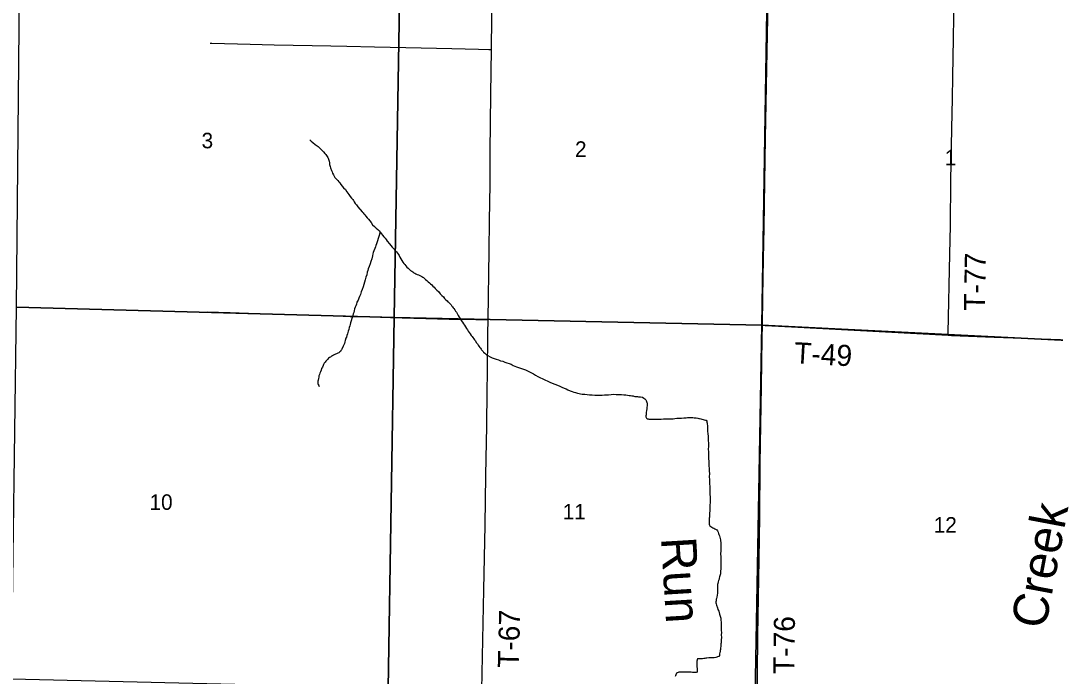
# Model space of a CAD drawing. Extents: x 1587405 to 1714697, y 1028970 to 1155083.
# Drawn here: x 1634826 to 1649563, y 1082468 to 1091803 of the extents above; entities that cross this region are included whole.
import ezdxf

# ---------------------------------------------------------------- set-up
doc = ezdxf.new("R2010")
doc.units = 0
for name, color, linetype in [('GM_X_Minor_River', 7, 'Continuous'), ('GM_X_Minor_River_Text', 7, 'Continuous'), ('GM_X_Section', 7, 'Continuous'), ('GM_X_Section_Text', 7, 'Continuous'), ('GM_X_Township_Road', 7, 'Continuous'), ('GM_X_Township_Road_Text', 7, 'Continuous')]:
    doc.layers.add(name, color=color, linetype=linetype)

msp = doc.modelspace()

# ---------------------------------------------------------------- linework, layer by layer
at = {"layer": 'GM_X_Minor_River'}
for points in [[(1638945, 1090105), (1638963, 1090089), (1638987, 1090067), (1639021, 1090042), (1639061, 1090012), (1639085, 1089989), (1639107, 1089967), (1639127, 1089951), (1639141, 1089934), (1639157, 1089914), (1639173, 1089896), (1639184, 1089882), (1639192, 1089870), (1639200, 1089857), (1639204, 1089847), (1639210, 1089831), (1639216, 1089819), (1639220, 1089801), (1639224, 1089779), (1639227, 1089753), (1639233, 1089726), (1639237, 1089708), (1639243, 1089692), (1639247, 1089682), (1639253, 1089668), (1639261, 1089650), (1639268, 1089632), (1639282, 1089607), (1639292, 1089589), (1639302, 1089571), (1639314, 1089557), (1639324, 1089547), (1639332, 1089537), (1639342, 1089526), (1639356, 1089510), (1639370, 1089492), (1639387, 1089470), (1639407, 1089447), (1639425, 1089421), (1639451, 1089397), (1639473, 1089364), (1639499, 1089330), (1639520, 1089299), (1639540, 1089275), (1639556, 1089257), (1639566, 1089241), (1639578, 1089222), (1639592, 1089202), (1639608, 1089180), (1639630, 1089152), (1639691, 1089083), (1639703, 1089068), (1639715, 1089054), (1639729, 1089038), (1639743, 1089020), (1639761, 1088998), (1639781, 1088975), (1639798, 1088953), (1639816, 1088929), (1639838, 1088896), (1639868, 1088874), (1639890, 1088849), (1639912, 1088829), (1639932, 1088811), (1639948, 1088793), (1639963, 1088770), (1639981, 1088748), (1639997, 1088726), (1640017, 1088705), (1640031, 1088687), (1640047, 1088665), (1640079, 1088628), (1640100, 1088604), (1640118, 1088580), (1640140, 1088555), (1640160, 1088533), (1640178, 1088513), (1640194, 1088495), (1640206, 1088476), (1640216, 1088458), (1640227, 1088436), (1640239, 1088414), (1640253, 1088387), (1640269, 1088367), (1640285, 1088347), (1640299, 1088331), (1640313, 1088312), (1640327, 1088294), (1640344, 1088280), (1640360, 1088264), (1640380, 1088247), (1640398, 1088237), (1640412, 1088225), (1640426, 1088215), (1640442, 1088207), (1640454, 1088198), (1640474, 1088188), (1640490, 1088182), (1640538, 1088161), (1640552, 1088153), (1640564, 1088145)], [(1639948, 1088793), (1639902, 1088654), (1639898, 1088640), (1639892, 1088624), (1639885, 1088604), (1639879, 1088582), (1639848, 1088504), (1639844, 1088484), (1639836, 1088454), (1639827, 1088414), (1639815, 1088374), (1639802, 1088340), (1639788, 1088302), (1639776, 1088272), (1639769, 1088248), (1639763, 1088220), (1639755, 1088184), (1639744, 1088150), (1639734, 1088114), (1639724, 1088080), (1639713, 1088048), (1639703, 1088014), (1639690, 1087977), (1639676, 1087941), (1639664, 1087905), (1639651, 1087877), (1639641, 1087851), (1639631, 1087825), (1639616, 1087793), (1639608, 1087769), (1639600, 1087745), (1639591, 1087723), (1639583, 1087699), (1639575, 1087673), (1639569, 1087649), (1639562, 1087627), (1639556, 1087605), (1639550, 1087585), (1639542, 1087561), (1639535, 1087529), (1639525, 1087503), (1639517, 1087479), (1639512, 1087459), (1639504, 1087433), (1639498, 1087405), (1639492, 1087383), (1639485, 1087363), (1639479, 1087343), (1639471, 1087321), (1639465, 1087299), (1639458, 1087281), (1639448, 1087251), (1639442, 1087229), (1639436, 1087209), (1639427, 1087189), (1639421, 1087169), (1639401, 1087125), (1639395, 1087115), (1639388, 1087105), (1639382, 1087095), (1639368, 1087081), (1639358, 1087075), (1639342, 1087067), (1639332, 1087063), (1639322, 1087059), (1639312, 1087055), (1639301, 1087049), (1639291, 1087045), (1639281, 1087039), (1639269, 1087033), (1639253, 1087024), (1639241, 1087014), (1639227, 1087006), (1639212, 1086996), (1639200, 1086982), (1639186, 1086970), (1639174, 1086954), (1639162, 1086940), (1639151, 1086926), (1639141, 1086910), (1639133, 1086894), (1639125, 1086872), (1639113, 1086850), (1639104, 1086826), (1639096, 1086804), (1639088, 1086784), (1639082, 1086764), (1639075, 1086744), (1639071, 1086726), (1639067, 1086706), (1639063, 1086686), (1639059, 1086668), (1639058, 1086656), (1639058, 1086644), (1639060, 1086634), (1639064, 1086622), (1639072, 1086608), (1639078, 1086593)], [(1640564, 1088145), (1640576, 1088131), (1640594, 1088117), (1640612, 1088102), (1640628, 1088086), (1640648, 1088070), (1640664, 1088056), (1640680, 1088041), (1640698, 1088025), (1640714, 1088009), (1640732, 1087991), (1640753, 1087968), (1640775, 1087946), (1640803, 1087913), (1640827, 1087889), (1640847, 1087869), (1640865, 1087848), (1640883, 1087828), (1640899, 1087814), (1640909, 1087802), (1640921, 1087794), (1640932, 1087781), (1640942, 1087771), (1640956, 1087759), (1640962, 1087749), (1640966, 1087739), (1640976, 1087727), (1640986, 1087715), (1640996, 1087704), (1641010, 1087686), (1641020, 1087668), (1641032, 1087652), (1641042, 1087632), (1641055, 1087607), (1641071, 1087583), (1641087, 1087561), (1641101, 1087536), (1641119, 1087510), (1641135, 1087488), (1641146, 1087466), (1641160, 1087443), (1641174, 1087419), (1641190, 1087401), (1641202, 1087383), (1641214, 1087362), (1641230, 1087342), (1641244, 1087322), (1641257, 1087304), (1641291, 1087259), (1641303, 1087243), (1641315, 1087223), (1641333, 1087200), (1641343, 1087184), (1641353, 1087170), (1641366, 1087152), (1641374, 1087138), (1641384, 1087126), (1641392, 1087115), (1641398, 1087105), (1641412, 1087093), (1641420, 1087083), (1641436, 1087069), (1641450, 1087055), (1641460, 1087048), (1641480, 1087034), (1641512, 1087016), (1641544, 1087003), (1641570, 1086993), (1641600, 1086985), (1641630, 1086972), (1641662, 1086962), (1641694, 1086954), (1641724, 1086941), (1641752, 1086931), (1641782, 1086920), (1641810, 1086912), (1641840, 1086894), (1641890, 1086875), (1641932, 1086861), (1641974, 1086848), (1642015, 1086834), (1642047, 1086817), (1642072, 1086803), (1642100, 1086788), (1642128, 1086774), (1642158, 1086758), (1642190, 1086739), (1642222, 1086723), (1642264, 1086702), (1642362, 1086655), (1642397, 1086643), (1642433, 1086626), (1642471, 1086612), (1642505, 1086597), (1642535, 1086587), (1642565, 1086573), (1642595, 1086560), (1642619, 1086546), (1642653, 1086535), (1642679, 1086523), (1642705, 1086515)], [(1642705, 1086515), (1642727, 1086509), (1642743, 1086504), (1642759, 1086500), (1642779, 1086496), (1642801, 1086490), (1642823, 1086487), (1642843, 1086487), (1642863, 1086485), (1642897, 1086481), (1642929, 1086476), (1642964, 1086474), (1643002, 1086472), (1643040, 1086471), (1643076, 1086471), (1643108, 1086470), (1643140, 1086474), (1643171, 1086476), (1643201, 1086477), (1643235, 1086479), (1643265, 1086483), (1643307, 1086482), (1643346, 1086482), (1643382, 1086480), (1643416, 1086477), (1643444, 1086475), (1643470, 1086473), (1643492, 1086468), (1643514, 1086466), (1643530, 1086462), (1643548, 1086460), (1643560, 1086456), (1643574, 1086453), (1643586, 1086453), (1643596, 1086451), (1643611, 1086451), (1643625, 1086449), (1643641, 1086447), (1643655, 1086447), (1643683, 1086442), (1643701, 1086430), (1643717, 1086418), (1643729, 1086406), (1643737, 1086395), (1643740, 1086381), (1643746, 1086367), (1643748, 1086355), (1643748, 1086339), (1643750, 1086323), (1643746, 1086297), (1643743, 1086275), (1643741, 1086255), (1643737, 1086225), (1643737, 1086205), (1643735, 1086193), (1643732, 1086176), (1643732, 1086164), (1643734, 1086154), (1643740, 1086142), (1643750, 1086136), (1643762, 1086132), (1643774, 1086130), (1643788, 1086128), (1643806, 1086128), (1643830, 1086127), (1643857, 1086127), (1643885, 1086129), (1643917, 1086128), (1643949, 1086130), (1643983, 1086132), (1644029, 1086133), (1644062, 1086133), (1644092, 1086135), (1644118, 1086136), (1644144, 1086140), (1644174, 1086144), (1644206, 1086143), (1644239, 1086145), (1644273, 1086149), (1644305, 1086150), (1644323, 1086152), (1644347, 1086154), (1644399, 1086151), (1644420, 1086149), (1644438, 1086149), (1644448, 1086147), (1644472, 1086143), (1644486, 1086140), (1644496, 1086138), (1644512, 1086134), (1644530, 1086130), (1644548, 1086126), (1644562, 1086122), (1644578, 1086117), (1644590, 1086115), (1644598, 1086099), (1644600, 1086087), (1644602, 1086073), (1644604, 1086059), (1644607, 1086041), (1644607, 1086021)], [(1644607, 1086021), (1644609, 1085994), (1644611, 1085958), (1644612, 1085922), (1644616, 1085888), (1644618, 1085858), (1644619, 1085826), (1644621, 1085789), (1644621, 1085741), (1644620, 1085703), (1644622, 1085665), (1644621, 1085629), (1644623, 1085594), (1644625, 1085566), (1644626, 1085532), (1644628, 1085492), (1644630, 1085458), (1644632, 1085430), (1644633, 1085395), (1644635, 1085353), (1644634, 1085311), (1644636, 1085265), (1644637, 1085213), (1644641, 1085166), (1644643, 1085126), (1644644, 1085096), (1644644, 1085074), (1644645, 1085004), (1644645, 1084983), (1644645, 1084955), (1644645, 1084935), (1644643, 1084913), (1644642, 1084893), (1644642, 1084873), (1644642, 1084855), (1644642, 1084837), (1644640, 1084817), (1644637, 1084797), (1644637, 1084777), (1644635, 1084756), (1644635, 1084732), (1644633, 1084718), (1644632, 1084702), (1644632, 1084690), (1644632, 1084674), (1644632, 1084658), (1644634, 1084644), (1644634, 1084634), (1644638, 1084620), (1644644, 1084610), (1644656, 1084600), (1644670, 1084591), (1644685, 1084581), (1644697, 1084575), (1644711, 1084569), (1644723, 1084563), (1644733, 1084557), (1644743, 1084552), (1644753, 1084540), (1644761, 1084518), (1644767, 1084502), (1644771, 1084486), (1644779, 1084468), (1644785, 1084447), (1644791, 1084431), (1644794, 1084413), (1644796, 1084395), (1644800, 1084375), (1644800, 1084351), (1644800, 1084321), (1644797, 1084287), (1644797, 1084246), (1644796, 1084220), (1644798, 1084160), (1644800, 1084144), (1644800, 1084128), (1644799, 1084108), (1644799, 1084090), (1644799, 1084066), (1644799, 1084037), (1644798, 1083995), (1644794, 1083969), (1644794, 1083953), (1644794, 1083941), (1644792, 1083927), (1644789, 1083911), (1644785, 1083897), (1644781, 1083883), (1644777, 1083867), (1644773, 1083849), (1644767, 1083833), (1644760, 1083813), (1644754, 1083789), (1644752, 1083773), (1644752, 1083761), (1644752, 1083749), (1644752, 1083739), (1644751, 1083724), (1644753, 1083704), (1644753, 1083680), (1644753, 1083652)], [(1644753, 1083652), (1644748, 1083622), (1644742, 1083596), (1644738, 1083578), (1644734, 1083566), (1644732, 1083554), (1644730, 1083542), (1644727, 1083530), (1644729, 1083514), (1644731, 1083498), (1644735, 1083482), (1644741, 1083469), (1644745, 1083457), (1644751, 1083441), (1644757, 1083421), (1644768, 1083395), (1644774, 1083375), (1644780, 1083354), (1644786, 1083340), (1644790, 1083326), (1644794, 1083312), (1644797, 1083296), (1644799, 1083280), (1644803, 1083224), (1644805, 1083197), (1644804, 1083177), (1644804, 1083149), (1644804, 1083121), (1644806, 1083091), (1644805, 1083057), (1644807, 1083021), (1644804, 1082986), (1644802, 1082960), (1644802, 1082944), (1644800, 1082930), (1644800, 1082914), (1644798, 1082892), (1644795, 1082872), (1644793, 1082852), (1644789, 1082834), (1644787, 1082818), (1644785, 1082808), (1644782, 1082788), (1644780, 1082772), (1644778, 1082762), (1644770, 1082752), (1644752, 1082744), (1644742, 1082740), (1644728, 1082736), (1644706, 1082732), (1644681, 1082731), (1644655, 1082729), (1644629, 1082729), (1644601, 1082727), (1644585, 1082724), (1644573, 1082722), (1644557, 1082720), (1644537, 1082718), (1644518, 1082718), (1644504, 1082718), (1644492, 1082718), (1644482, 1082719), (1644468, 1082717), (1644456, 1082685), (1644456, 1082657), (1644457, 1082614), (1644461, 1082568), (1644462, 1082538), (1644462, 1082526), (1644448, 1082524), (1644438, 1082524), (1644424, 1082524), (1644408, 1082524), (1644394, 1082523), (1644376, 1082525), (1644346, 1082525), (1644316, 1082527), (1644287, 1082528), (1644259, 1082528), (1644229, 1082528), (1644213, 1082527), (1644199, 1082525), (1644189, 1082523), (1644177, 1082519), (1644167, 1082511), (1644159, 1082491), (1644152, 1082477), (1644148, 1082463)]]:
    msp.add_lwpolyline(points, dxfattribs=at)
at = {"layer": 'GM_X_Section'}
for points in [[(1634815, 1092707), (1634837, 1092707), (1640169, 1092626), (1640231, 1092623), (1640147, 1087579), (1634766, 1087725)], [(1640231, 1092623), (1645465, 1092544), (1645381, 1087470), (1640147, 1087579)], [(1645465, 1092544), (1650761, 1092453), (1650692, 1087357), (1650688, 1087203), (1645381, 1087470)], [(1634766, 1087725), (1640147, 1087579), (1640062, 1082297), (1634697, 1082425)], [(1640147, 1087579), (1645381, 1087470), (1645287, 1082186), (1640062, 1082297)], [(1645381, 1087470), (1650688, 1087203), (1650640, 1082028), (1650639, 1081906), (1645287, 1082186)]]:
    msp.add_lwpolyline(points, close=True, dxfattribs=at)
at = {"layer": 'GM_X_Township_Road'}
for points in [[(1641532, 1091394), (1641540, 1092297), (1641545, 1092605)], [(1645390, 1087466), (1645397, 1087872), (1645407, 1088414), (1645414, 1088856), (1645421, 1089184), (1645433, 1090134), (1645458, 1091364), (1645466, 1091840), (1645471, 1092283), (1645474, 1092479), (1645475, 1092546)], [(1648077, 1089521), (1648089, 1090267), (1648098, 1090694), (1648103, 1091006), (1648111, 1091548), (1648126, 1092467), (1648126, 1092488)], [(1637525, 1091482), (1637551, 1091481), (1638093, 1091468), (1638438, 1091461), (1638980, 1091451), (1639243, 1091446), (1639473, 1091440), (1639867, 1091432), (1640311, 1091422), (1640968, 1091408), (1641346, 1091396), (1641494, 1091394), (1641532, 1091394)], [(1641505, 1088954), (1641513, 1089476), (1641514, 1089935), (1641521, 1090755), (1641532, 1091394)], [(1648037, 1087325), (1648038, 1087360), (1648060, 1088477), (1648068, 1088887), (1648077, 1089521)], [(1641484, 1087549), (1641499, 1088524), (1641505, 1088954)], [(1637480, 1087656), (1637809, 1087647), (1638333, 1087630), (1638692, 1087620), (1638840, 1087615), (1639016, 1087608), (1639213, 1087603), (1639521, 1087592), (1639669, 1087589), (1640095, 1087575), (1640930, 1087555), (1641307, 1087550), (1641453, 1087549), (1641484, 1087549)], [(1641393, 1082250), (1641393, 1082274), (1641423, 1083701), (1641440, 1084620), (1641451, 1085325), (1641457, 1085571), (1641464, 1086031), (1641472, 1086539), (1641475, 1086785), (1641481, 1087343), (1641484, 1087549)], [(1645317, 1082175), (1645317, 1082214), (1645319, 1082493), (1645327, 1083051), (1645344, 1084133), (1645352, 1084740), (1645360, 1085494), (1645379, 1086593), (1645387, 1087282), (1645390, 1087466)], [(1645390, 1087466), (1645432, 1087464), (1645807, 1087446), (1648037, 1087325)], [(1648037, 1087325), (1648086, 1087322), (1648693, 1087297), (1650039, 1087249), (1650301, 1087230), (1650678, 1087215), (1650710, 1087214)]]:
    msp.add_lwpolyline(points, dxfattribs=at)

# ---------------------------------------------------------------- texts
at = {"layer": 'GM_X_Minor_River_Text'}
for s, rotation, p in [('Creek', 79.3151, (1649420, 1083127)), ('Run', 273.4451, (1643946, 1084438))]:
    msp.add_text(s, height=500.2, rotation=rotation, dxfattribs=at).set_placement(p)
at = {"layer": 'GM_X_Section_Text'}
for s, p in [('3', (1637403, 1089986)), ('2', (1642722, 1089864)), ('1', (1647989, 1089744)), ('10', (1636661, 1084838)), ('11', (1642546, 1084701)), ('12', (1647831, 1084514))]:
    msp.add_text(s, height=221, rotation=0, dxfattribs=at).set_placement(p)
at = {"layer": 'GM_X_Township_Road_Text'}
for s, rotation, p in [('T-77', 88.9383, (1648560, 1087670)), ('T-49', 356.8205, (1645837, 1086927)), ('T-67', 88.5864, (1641921, 1082585)), ('T-76', 89.2917, (1645845, 1082499))]:
    msp.add_text(s, height=300, rotation=rotation, dxfattribs=at).set_placement(p)

doc.saveas('drawing.dxf')
